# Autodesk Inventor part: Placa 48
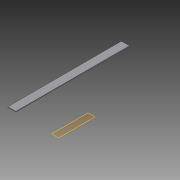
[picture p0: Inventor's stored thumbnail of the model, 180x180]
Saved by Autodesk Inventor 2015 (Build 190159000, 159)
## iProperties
Created: 2015-04
Part Number: Placa 48
Material: Generic
Document SubType Name: Modeling
Designer: suporte
Density: 1 g/cm^3
Appearance: Default
Author: suporte
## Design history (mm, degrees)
workplane "Work Plane1"
sketch "Sketch1"
  geometry: L1 (-650, -262.5)-(-775, -262.5); L2 (-775, -262.5)-(-775, 1537.5); L3 (-775, 1537.5)-(-650, 1537.5); L4 (-650, 1537.5)-(-650, -262.5); 1 further point
  constraints: 8 end point, 2 parallel, 1 horizontal, 1 perpendicular, 2 other
extrude "Extrusion1" new body sketch "Sketch1" distance "d0" = 12.5; taper "d1" = 0 deg
body "Solid1"
